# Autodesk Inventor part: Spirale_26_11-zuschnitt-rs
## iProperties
Created: 2004-11
Part Number: Spirale_26_11-zuschnitt-rs
Material: .
Document SubType Name: Modeling
Designer: rsc
Manufacturer: Standard
Standards Organization: Custom
Kanten: brechen
Oberflächen: Ra 3,2
Radien: 2
Toleranzen: ISO 2768 - m
Author: rsc
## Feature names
1. Extrusion1
